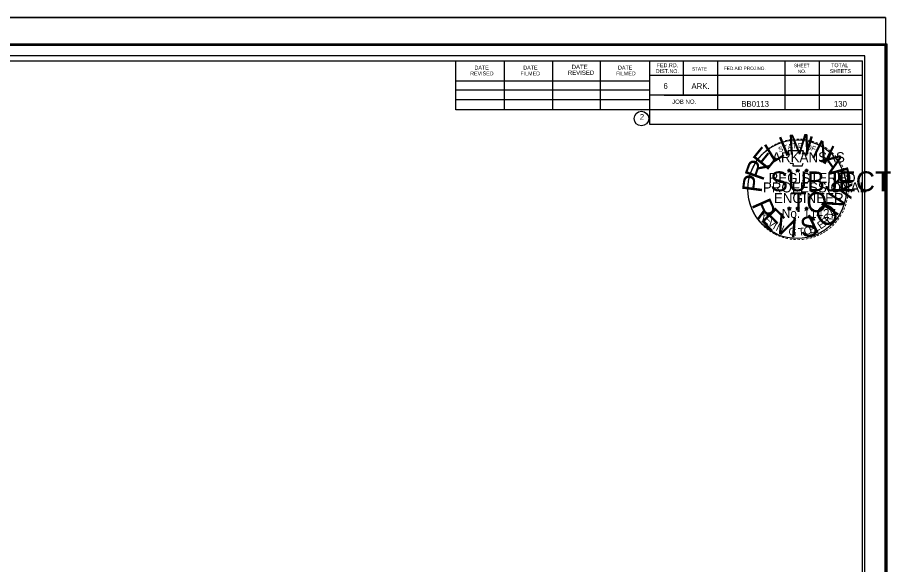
# Model space of a CAD drawing. Extents: x -0.4 to 35.1, y -0.1 to 22.2.
# Drawn here: x 17.38 to 35.11, y 11.04 to 22.15 of the extents above; entities that cross this region are included whole.
import ezdxf

# ---------------------------------------------------------------- set-up
doc = ezdxf.new("R2010")
doc.units = 0
for name, color, linetype in [('Level 1', 7, 'Continuous'), ('NO PLOT', 7, 'Continuous'), ('Plot_Normal', 7, 'Continuous'), ('Plot_PDF', 7, 'Continuous'), ('R_Border', 7, 'Continuous'), ('R_Border Notes', 7, 'Continuous'), ('R_Border PE', 7, 'Continuous'), ('R_Border Prem', 7, 'Continuous'), ('R_No Plot', 7, 'Continuous')]:
    doc.layers.add(name, color=color, linetype=linetype)

msp = doc.modelspace()

# ---------------------------------------------------------------- linework, layer by layer
at = {"layer": 'Level 1'}
for p in [(2.529, 21.272), (34.54, 0.726)]:
    msp.add_line(p, (34.54, 21.272), dxfattribs=at)
at = {"layer": 'NO PLOT'}
msp.add_line((34.991, 21.591), (1.646, 21.591), dxfattribs=at)
at = {"layer": 'Plot_Normal'}
msp.add_lwpolyline([(1.684, 21.619), (35.029, 21.619), (35.029, 0.379), (1.684, 0.379)], close=True, dxfattribs=at)
at = {"layer": 'Plot_PDF'}
msp.add_lwpolyline([(1.631, 0.439), (34.585, 0.439), (34.585, 21.373), (1.631, 21.373)], close=True, dxfattribs=at)
at = {"layer": 'R_Border'}
for p, q in [((35.002, 22.153), (-0.352, 22.153)), ((26.278, 20.28), (26.278, 21.272)), ((27.268, 20.28), (27.268, 21.252)), ((28.249, 20.28), (28.249, 21.252)), ((29.221, 20.28), (29.221, 21.252)), ((30.211, 21.272), (30.211, 19.986)), ((30.898, 21.272), (30.898, 20.575)), ((31.595, 21.272), (31.595, 20.28)), ((32.959, 21.272), (32.959, 20.28)), ((33.656, 21.272), (33.656, 20.28)), ((34.54, 20.977), (30.211, 20.977)), ((26.278, 20.868), (30.211, 20.868)), ((26.278, 20.681), (30.211, 20.681)), ((34.54, 20.575), (30.211, 20.575)), ((30.508, 20.575), (34.54, 20.575)), ((26.278, 20.28), (26.278, 20.487)), ((26.278, 20.487), (30.211, 20.487)), ((34.54, 20.28), (26.278, 20.28)), ((30.211, 19.986), (34.54, 19.986))]:
    msp.add_line(p, q, dxfattribs=at)
msp.add_circle((30.049, 20.1), 0.147, dxfattribs=at)
at = {"layer": 'R_Border PE'}
for p, q in [((33.016, 19.053), (33.052, 19.042)), ((33.016, 19.053), (33.042, 19.048)), ((33.016, 19.053), (33.04, 19.041)), ((33.03, 19.012), (33.052, 19.042)), ((33.03, 19.012), (33.043, 19.036)), ((33.03, 19.012), (33.052, 19.034)), ((33.052, 19.079), (33.048, 19.053)), ((33.052, 19.042), (33.052, 19.079)), ((33.052, 19.079), (33.057, 19.053)), ((33.087, 19.053), (33.052, 19.042)), ((33.073, 19.012), (33.052, 19.042)), ((33.073, 19.012), (33.052, 19.033)), ((33.087, 19.053), (33.058, 19.048)), ((33.073, 19.012), (33.059, 19.041)), ((33.087, 19.053), (33.066, 19.043)), ((33.186, 19.053), (33.221, 19.042)), ((33.186, 19.053), (33.212, 19.048)), ((33.186, 19.053), (33.21, 19.041)), ((33.199, 19.012), (33.221, 19.042)), ((33.199, 19.012), (33.212, 19.036)), ((33.199, 19.012), (33.221, 19.034)), ((33.221, 19.079), (33.217, 19.053)), ((33.221, 19.042), (33.221, 19.079)), ((33.221, 19.079), (33.226, 19.053)), ((33.257, 19.053), (33.221, 19.042)), ((33.243, 19.012), (33.221, 19.042)), ((33.243, 19.012), (33.221, 19.033)), ((33.257, 19.053), (33.227, 19.048)), ((33.243, 19.012), (33.229, 19.041)), ((33.257, 19.053), (33.236, 19.043)), ((33.365, 19.052), (33.4, 19.04)), ((33.365, 19.052), (33.391, 19.047)), ((33.365, 19.052), (33.389, 19.039)), ((33.378, 19.01), (33.4, 19.04)), ((33.378, 19.01), (33.391, 19.035)), ((33.378, 19.01), (33.4, 19.032)), ((33.4, 19.078), (33.396, 19.052)), ((33.4, 19.04), (33.4, 19.078)), ((33.4, 19.078), (33.405, 19.052)), ((33.436, 19.052), (33.4, 19.04)), ((33.422, 19.01), (33.4, 19.04)), ((33.422, 19.01), (33.4, 19.032)), ((33.436, 19.052), (33.407, 19.047)), ((33.422, 19.01), (33.408, 19.04)), ((33.436, 19.052), (33.415, 19.041)), ((33.016, 18.284), (33.051, 18.273)), ((33.016, 18.284), (33.042, 18.279)), ((33.016, 18.284), (33.04, 18.272)), ((33.029, 18.242), (33.051, 18.273)), ((33.029, 18.242), (33.042, 18.267)), ((33.029, 18.242), (33.051, 18.265)), ((33.051, 18.31), (33.047, 18.284)), ((33.051, 18.273), (33.051, 18.31)), ((33.051, 18.31), (33.056, 18.284)), ((33.087, 18.284), (33.051, 18.273)), ((33.073, 18.242), (33.051, 18.273)), ((33.073, 18.242), (33.051, 18.264)), ((33.087, 18.284), (33.057, 18.279)), ((33.073, 18.242), (33.059, 18.272)), ((33.087, 18.284), (33.066, 18.274)), ((33.185, 18.284), (33.221, 18.273)), ((33.185, 18.284), (33.211, 18.279)), ((33.185, 18.284), (33.209, 18.272)), ((33.199, 18.242), (33.221, 18.273)), ((33.199, 18.242), (33.212, 18.267)), ((33.199, 18.242), (33.221, 18.265)), ((33.221, 18.31), (33.217, 18.284)), ((33.221, 18.273), (33.221, 18.31)), ((33.221, 18.31), (33.226, 18.284)), ((33.256, 18.284), (33.221, 18.273)), ((33.242, 18.242), (33.221, 18.273)), ((33.242, 18.242), (33.221, 18.264)), ((33.256, 18.284), (33.227, 18.279)), ((33.242, 18.242), (33.229, 18.272)), ((33.256, 18.284), (33.235, 18.274)), ((33.365, 18.283), (33.4, 18.272)), ((33.365, 18.283), (33.39, 18.278)), ((33.365, 18.283), (33.389, 18.271)), ((33.378, 18.241), (33.4, 18.272)), ((33.378, 18.241), (33.391, 18.266)), ((33.378, 18.241), (33.4, 18.264)), ((33.4, 18.309), (33.396, 18.283)), ((33.4, 18.272), (33.4, 18.309)), ((33.4, 18.309), (33.405, 18.283)), ((33.435, 18.283), (33.4, 18.272)), ((33.422, 18.241), (33.4, 18.272)), ((33.422, 18.241), (33.4, 18.263)), ((33.435, 18.283), (33.406, 18.278)), ((33.422, 18.241), (33.408, 18.271)), ((33.435, 18.283), (33.415, 18.273))]:
    msp.add_line(p, q, dxfattribs=at)
for points in [[(33.02, 19.447), (33.048, 19.363)], [(33.377, 19.353), (33.391, 19.382), (33.322, 19.38), (33.337, 19.447), (33.02, 19.447)], [(33.07, 19.201), (33.07, 19.192), (33.128, 19.19), (33.122, 19.142), (33.312, 19.142), (33.332, 19.196)], [(33.052, 19.079), (33.073, 19.012), (33.016, 19.053), (33.087, 19.053), (33.03, 19.012), (33.052, 19.079)], [(33.221, 19.079), (33.243, 19.012), (33.186, 19.053), (33.257, 19.053), (33.199, 19.012), (33.221, 19.079)], [(33.4, 19.078), (33.422, 19.01), (33.365, 19.052), (33.436, 19.052), (33.378, 19.01), (33.4, 19.078)], [(33.051, 18.31), (33.073, 18.242), (33.016, 18.284), (33.087, 18.284), (33.029, 18.242), (33.051, 18.31)], [(33.221, 18.31), (33.242, 18.242), (33.185, 18.284), (33.256, 18.284), (33.199, 18.242), (33.221, 18.31)], [(33.4, 18.309), (33.422, 18.241), (33.365, 18.283), (33.435, 18.283), (33.378, 18.241), (33.4, 18.309)]]:
    msp.add_lwpolyline(points, dxfattribs=at)
for centre, radius in [((33.052, 19.042), 0.0175), ((33.052, 19.042), 0.0147), ((33.052, 19.042), 0.0118), ((33.052, 19.042), 0.0101), ((33.052, 19.042), 0.00759), ((33.052, 19.042), 0.00503), ((33.052, 19.042), 0.00301), ((33.221, 19.042), 0.0175), ((33.221, 19.042), 0.0147), ((33.221, 19.042), 0.0118), ((33.221, 19.042), 0.0101), ((33.221, 19.042), 0.00759), ((33.221, 19.042), 0.00503), ((33.221, 19.042), 0.00301), ((33.4, 19.04), 0.0175), ((33.4, 19.04), 0.0147), ((33.4, 19.04), 0.0118), ((33.4, 19.04), 0.0101), ((33.4, 19.04), 0.00759), ((33.4, 19.04), 0.00503), ((33.4, 19.04), 0.00301), ((33.051, 18.273), 0.0175), ((33.051, 18.273), 0.0147), ((33.051, 18.273), 0.0118), ((33.051, 18.273), 0.0101), ((33.051, 18.273), 0.00759), ((33.051, 18.273), 0.00503), ((33.051, 18.273), 0.00301), ((33.221, 18.273), 0.0175), ((33.221, 18.273), 0.0147), ((33.221, 18.273), 0.0118), ((33.221, 18.273), 0.0101), ((33.221, 18.273), 0.00759), ((33.221, 18.273), 0.00503), ((33.221, 18.273), 0.00301), ((33.4, 18.272), 0.0175), ((33.4, 18.272), 0.0147), ((33.4, 18.272), 0.0118), ((33.4, 18.272), 0.0101), ((33.4, 18.272), 0.00759), ((33.4, 18.272), 0.00503), ((33.4, 18.272), 0.00301)]:
    msp.add_circle(centre, radius, dxfattribs=at)
at = {"layer": 'R_Border Prem'}
msp.add_circle((33.212, 18.665), 1.002, dxfattribs=at)
at = {"layer": 'R_No Plot'}
for points in [[(-0.352, 22.153), (35.002, 22.153), (35.002, -0.065), (-0.352, -0.065)], [(1.646, 21.591), (34.991, 21.591), (34.991, 0.499), (1.646, 0.499)]]:
    msp.add_lwpolyline(points, close=True, dxfattribs=at)

# ---------------------------------------------------------------- texts
at = {"layer": 'R_Border Notes'}
for s, height, p in [('DATE', 0.0785, (26.66, 21.095)), ('DATE', 0.0785, (27.65, 21.095)), ('DATE', 0.0883, (28.632, 21.105)), ('DATE', 0.0785, (29.574, 21.095)), ('DIST.NO.', 0.0785, (30.34, 21.025)), ('FED.RD.', 0.0785, (30.36, 21.143)), ('STATE', 0.0687, (31.075, 21.075)), ('FED.AID PROJ.NO.', 0.0687, (31.724, 21.085)), ('SHEET', 0.0687, (33.146, 21.143)), ('SHEETS', 0.0785, (33.873, 21.025)), ('TOTAL', 0.0785, (33.901, 21.143)), ('REVISED', 0.0785, (26.571, 20.977)), ('FILMED', 0.0785, (27.592, 20.977)), ('REVISED', 0.0883, (28.554, 20.987)), ('FILMED', 0.0785, (29.534, 20.977)), ('NO.', 0.0687, (33.224, 21.025)), ('6', 0.118, (30.496, 20.702)), ('ARK.', 0.1177, (31.065, 20.702)), ('JOB NO.', 0.0883, (30.673, 20.398)), ('BB0113', 0.1178, (32.078, 20.34)), ('130', 0.1178, (33.959, 20.34)), ('2', 0.118, (30.016, 20.075))]:
    msp.add_text(s, height=height, dxfattribs=at).set_placement(p)
at = {"layer": 'R_Border PE'}
for s, height, rotation, p in [('-', 0.162, 10.2193, (33.038, 19.602)), ('-', 0.162, 5.8968, (33.112, 19.613)), ('-', 0.162, 0.1862, (33.191, 19.621)), ('-', 0.162, 357.743, (33.264, 19.619)), ('-', 0.162, 352.1617, (33.34, 19.614)), ('-', 0.162, 36.2317, (32.645, 19.424)), ('-', 0.162, 34.0636, (32.704, 19.464)), ('-', 0.162, 28.7918, (32.765, 19.502)), ('-', 0.162, 24.3072, (32.829, 19.534)), ('S', 0.102, 21.594, (32.853, 19.414)), ('-', 0.162, 19.1761, (32.893, 19.561)), ('T', 0.102, 16.4036, (32.946, 19.448)), ('-', 0.162, 13.6302, (32.969, 19.586)), ('A', 0.102, 11.2132, (33.03, 19.473)), ('T', 0.102, 6.0228, (33.116, 19.49)), ('E', 0.102, 0.8323, (33.228, 19.501)), ('O', 0.102, 350.4515, (33.391, 19.48)), ('-', 0.162, 347.2049, (33.413, 19.602)), ('F', 0.102, 340.0707, (33.488, 19.457)), ('-', 0.162, 342.3362, (33.477, 19.586)), ('-', 0.162, 337.8551, (33.552, 19.564)), ('-', 0.162, 334.1211, (33.616, 19.536)), ('-', 0.162, 329.6409, (33.675, 19.507)), ('-', 0.162, 325.8627, (33.74, 19.471)), ('-', 0.162, 50.6142, (32.467, 19.245)), ('-', 0.162, 48.4231, (32.507, 19.295)), ('-', 0.162, 42.9622, (32.553, 19.343)), ('-', 0.162, 38.9507, (32.597, 19.386)), ('-', 0.162, 320.5297, (33.802, 19.427)), ('-', 0.162, 315.5786, (33.863, 19.378)), ('-', 0.162, 309.8797, (33.921, 19.322)), ('-', 0.162, 62.8713, (32.36, 19.072)), ('-', 0.162, 58.0706, (32.392, 19.134)), ('-', 0.162, 54.2325, (32.425, 19.188)), ('-', 0.162, 306.6522, (33.974, 19.261)), ('-', 0.142, 303.6753, (34.023, 19.203)), ('-', 0.162, 299.6684, (34.056, 19.142)), ('-', 0.162, 72.3945, (32.311, 18.946)), ('-', 0.162, 67.7743, (32.334, 19.01)), ('-', 0.162, 294.6628, (34.088, 19.079)), ('-', 0.162, 290.5728, (34.115, 19.021)), ('-', 0.162, 285.1233, (34.138, 18.962)), ('-', 0.162, 85.1863, (32.27, 18.731)), ('-', 0.162, 81.2013, (32.278, 18.801)), ('-', 0.162, 75.461, (32.291, 18.873)), ('-', 0.162, 280.5493, (34.159, 18.887)), ('-', 0.162, 276.5962, (34.175, 18.809)), ('-', 0.162, 94.1959, (32.271, 18.586)), ('-', 0.162, 89.0622, (32.268, 18.66)), ('-', 0.162, 274.3301, (34.181, 18.735)), ('-', 0.162, 269.9407, (34.185, 18.671)), ('-', 0.162, 98.9479, (32.279, 18.518)), ('-', 0.162, 101.7149, (32.292, 18.444)), ('-', 0.162, 255.7626, (34.164, 18.468)), ('-', 0.162, 260.9953, (34.176, 18.537)), ('-', 0.162, 263.5172, (34.183, 18.603)), ('-', 0.162, 105.4578, (32.309, 18.383)), ('-', 0.162, 109.0874, (32.33, 18.319)), ('-', 0.162, 114.0643, (32.356, 18.259)), ('-', 0.162, 247.8887, (34.123, 18.327)), ('-', 0.162, 252.8681, (34.146, 18.395)), ('-', 0.162, 115.7289, (32.387, 18.196)), ('-', 0.162, 120.4471, (32.424, 18.137)), ('-', 0.162, 125.8934, (32.464, 18.08)), ('K', 0.156, 308.8519, (32.44, 18.131)), ('E', 0.156, 316.5286, (32.518, 18.032)), ('S', 0.156, 41.8751, (33.782, 17.908)), ('K', 0.156, 47.4675, (33.853, 17.967)), ('Y', 0.156, 55.1442, (33.939, 18.058)), ('-', 0.162, 239.0712, (34.057, 18.187)), ('-', 0.162, 244.6197, (34.097, 18.263)), ('-', 0.162, 130.7181, (32.511, 18.024)), ('-', 0.162, 134.2238, (32.564, 17.968)), ('-', 0.162, 138.9338, (32.617, 17.921)), ('V', 0.156, 323.5106, (32.599, 17.952)), ('I', 0.156, 331.6042, (32.704, 17.872)), ('N', 0.156, 336.085, (32.767, 17.834)), ('O', 0.156, 13.9472, (33.366, 17.731)), ('B', 0.156, 21.2071, (33.482, 17.757)), ('L', 0.156, 27.9111, (33.585, 17.794)), ('E', 0.156, 34.8931, (33.687, 17.845)), ('-', 0.162, 221.0851, (33.871, 17.954)), ('-', 0.162, 225.7653, (33.924, 18.005)), ('-', 0.162, 231.2538, (33.972, 18.063)), ('-', 0.162, 233.8452, (34.016, 18.12)), ('-', 0.162, 144.6463, (32.674, 17.88)), ('-', 0.162, 148.0898, (32.731, 17.842)), ('-', 0.162, 151.5704, (32.789, 17.809)), ('-', 0.162, 154.6002, (32.842, 17.784)), ('-', 0.162, 158.5612, (32.906, 17.758)), ('G', 0.156, 353.1059, (33.027, 17.738)), ('.', 0.156, 0.6437, (33.149, 17.721)), ('T', 0.156, 6.2704, (33.241, 17.719)), ('-', 0.162, 204.2516, (33.641, 17.799)), ('-', 0.162, 207.3568, (33.704, 17.831)), ('-', 0.162, 212.2491, (33.761, 17.867)), ('-', 0.162, 215.7363, (33.815, 17.906)), ('-', 0.162, 162.7983, (32.976, 17.737)), ('-', 0.162, 167.5555, (33.048, 17.72)), ('-', 0.162, 173.1155, (33.127, 17.709)), ('-', 0.162, 176.5183, (33.202, 17.703)), ('-', 0.162, 181.5918, (33.278, 17.705)), ('-', 0.162, 185.8167, (33.36, 17.713)), ('-', 0.162, 191.2858, (33.435, 17.727)), ('-', 0.162, 195.4743, (33.509, 17.747)), ('-', 0.162, 200.7184, (33.578, 17.771))]:
    msp.add_text(s, height=height, rotation=rotation, dxfattribs=at).set_placement(p)
for s, height, p in [('ARKANSAS', 0.2031, (32.701, 19.214)), ('REGISTERED', 0.2031, (32.632, 18.793)), ('PROFESSIONAL', 0.2031, (32.515, 18.6)), ('ENGINEER', 0.2031, (32.738, 18.384)), ('No. 11427', 0.1784, (32.9, 18.084))]:
    msp.add_text(s, height=height, dxfattribs=at).set_placement(p)
at = {"layer": 'R_Border Prem'}
for s, rotation, p in [('I', 22.0105, (32.947, 19.321)), ('M', 2.6943, (33.035, 19.365)), ('I', 343.3781, (33.319, 19.372)), ('E', 50.9849, (32.594, 19.027)), ('L', 31.6686, (32.714, 19.189)), ('N', 333.7199, (33.478, 19.324)), ('A', 304.7456, (33.667, 19.252)), ('R', 70.3011, (32.514, 18.814)), ('R', 285.4294, (33.841, 19.048)), ('P', 82.6089, (32.487, 18.58)), ('Y', 266.1131, (33.934, 18.832)), ('R', 293.7639, (32.278, 18.36)), ('N', 57.1378, (34.009, 18.097)), ('E', 314.3262, (32.452, 18.044)), ('O', 36.5754, (33.765, 17.857)), ('V', 334.8885, (32.701, 17.825)), ('I', 355.4508, (33.056, 17.696)), ('S', 5.732, (33.29, 17.69)), ('I', 26.2943, (33.559, 17.746))]:
    msp.add_text(s, height=0.403, rotation=rotation, dxfattribs=at).set_placement(p)
for s, p in [('SUBJECT', (32.665, 18.624)), ('TO', (33.072, 18.201))]:
    msp.add_text(s, height=0.403, dxfattribs=at).set_placement(p)

doc.saveas('drawing.dxf')
